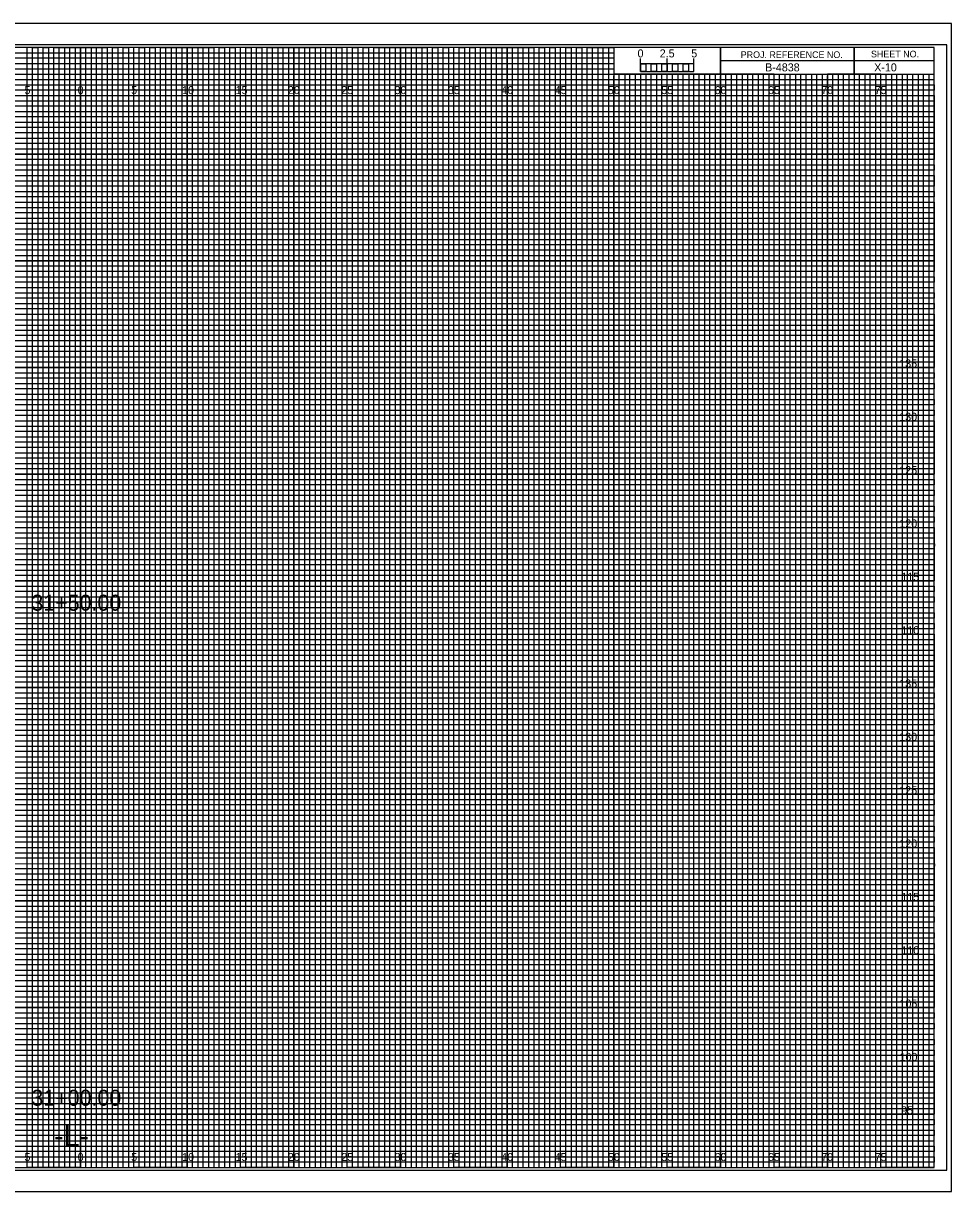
# Model space of a CAD drawing. Extents: x -7 to 182, y -2 to 1647.
# Drawn here: x 74.6 to 161.7, y 877.8 to 987.2 of the extents above; entities that cross this region are included whole.
import ezdxf

# ---------------------------------------------------------------- set-up
doc = ezdxf.new("R2010")
doc.units = 0
for name, color, linetype in [('Exist CMT Pavement', 7, 'Continuous'), ('Exist Cross Section Cell', 7, 'Continuous'), ('Exist XS Ground Line', 7, 'Continuous'), ('Prop CMT Pvmt Course 1', 7, 'Continuous'), ('Prop CMT Pvmt Course 2', 7, 'Continuous'), ('Prop CMT Pvmt Course 2 Wedge', 7, 'Continuous'), ('Prop CMT Pvmt Course 3', 7, 'Continuous'), ('Prop CMT Pvmt Surface', 7, 'Continuous'), ('Prop CMT Pvmt Surface Shoulder', 7, 'Continuous'), ('Prop CMT Pvmt Wedge Surface 1', 7, 'Continuous'), ('Prop CMT Pvmt Wedge Surface 2', 7, 'Continuous'), ('Prop CMT Pvmt Wedge Surface 3', 7, 'Continuous'), ('Prop CMT Shld Paved Course 1', 7, 'Continuous'), ('Prop CMT Shld Paved Course 2', 7, 'Continuous'), ('Prop CMT Shld Paved Course 3', 7, 'Continuous'), ('Prop CMT Slope Grass', 7, 'Continuous'), ('Prop CMT Subgrade Earthwork', 7, 'Continuous')]:
    doc.layers.add(name, color=color, linetype=linetype)

msp = doc.modelspace()

# ---------------------------------------------------------------- linework, layer by layer
at = {"layer": 'Exist XS Ground Line'}
for p, q in [((75, 985), (70, 985)), ((75, 880), (75, 985)), ((85, 985), (80, 985)), ((80, 985), (80, 880)), ((85, 880), (85, 985)), ((95, 985), (90, 985)), ((90, 985), (90, 880)), ((95, 880), (95, 985)), ((105, 985), (100, 985)), ((100, 985), (100, 880)), ((105, 880), (105, 985)), ((115, 985), (110, 985)), ((110, 985), (110, 880)), ((115, 880), (115, 985)), ((125, 985), (120, 985)), ((120, 985), (120, 880)), ((125, 880), (125, 985)), ((130, 985), (130, 880)), ((135, 880), (135, 982.5)), ((145, 982.5), (140, 982.5)), ((140, 982.5), (140, 880)), ((145, 880), (145, 982.5)), ((155, 982.5), (150, 982.5)), ((150, 982.5), (150, 880)), ((155, 880), (155, 982.5)), ((80, 880), (75, 880)), ((90, 880), (85, 880)), ((100, 880), (95, 880)), ((110, 880), (105, 880)), ((120, 880), (115, 880)), ((130, 880), (125, 880)), ((140, 880), (135, 880)), ((150, 880), (145, 880)), ((160, 880), (155, 880)), ((160, 880), (160, 880))]:
    msp.add_line(p, q, dxfattribs=at)
for points in [[(0, 980), (160, 980), (160, 975), (0, 975)], [(0, 970), (160, 970), (160, 965), (0, 965)], [(0, 960), (160, 960), (160, 955), (0, 955)], [(0, 950), (160, 950), (160, 945), (0, 945)], [(0, 940), (160, 940), (160, 935), (0, 935)], [(0, 930), (160, 930), (160, 925), (0, 925)], [(0, 920), (160, 920), (160, 915), (0, 915)], [(0, 910), (160, 910), (160, 905), (0, 905)], [(0, 900), (160, 900), (160, 895), (0, 895)], [(0, 890), (160, 890), (160, 885), (0, 885)]]:
    msp.add_lwpolyline(points, dxfattribs=at)
at = {"layer": 'Prop CMT Pvmt Course 2'}
for p, q in [((132.5, 982.75), (132.5, 983.95)), ((132.5, 983.45), (132.5, 983.95)), ((135, 982.75), (135, 983.95)), ((137.5, 982.75), (137.5, 983.95)), ((137.5, 983.45), (137.5, 983.95))]:
    msp.add_line(p, q, dxfattribs=at)
for points in [[(137.5, 983.45), (132.5, 983.45), (132.5, 982.75), (137.5, 982.75)], [(132.5, 983.45), (133, 983.45), (133, 982.75), (132.5, 982.75)], [(133.5, 983.45), (134, 983.45), (134, 982.75), (133.5, 982.75)], [(134.5, 983.45), (135, 983.45), (135, 982.75), (134.5, 982.75)], [(135.5, 983.45), (136, 983.45), (136, 982.75), (135.5, 982.75)], [(136.5, 983.45), (137, 983.45), (137, 982.75), (136.5, 982.75)]]:
    msp.add_lwpolyline(points, close=True, dxfattribs=at)
at = {"layer": 'Prop CMT Pvmt Course 3'}
msp.add_lwpolyline([(-6.7, 877.75), (161.65, 877.75), (161.65, 987.25), (-6.7, 987.25)], close=True, dxfattribs=at)
at = {"layer": 'Prop CMT Pvmt Wedge Surface 1'}
for p, q in [((0, 984.5), (130, 984.5)), ((130, 984.5), (130, 983.99)), ((130, 983.99), (0, 983.99)), ((0, 983.5), (130, 983.5)), ((130, 983.5), (130, 982.95)), ((130, 982.95), (0, 982.95)), ((0, 982), (160, 982))]:
    msp.add_line(p, q, dxfattribs=at)
for points in [[(0, 981.5), (135, 981.5), (160, 981.5), (160, 981), (0, 981)], [(0, 980.5), (160, 980.5), (160, 979.5), (0, 979.5)], [(0, 979), (160, 979), (160, 978.5), (0, 978.49)], [(0, 978), (160, 978), (160, 977), (0, 977)], [(0, 976.5), (160, 976.5), (160, 976), (0, 976)], [(0, 975.5), (160, 975.5), (160, 974.5), (0, 974.5)], [(0, 974), (160, 974), (160, 973.5), (0, 973.5)], [(0, 973), (160, 973), (160, 972), (0, 972)], [(0, 971.5), (160, 971.5), (160, 971), (0, 971)], [(0, 970.5), (160, 970.5), (160, 969.5), (0, 969.5)], [(0, 969), (160, 969), (160, 968.5), (0, 968.5)], [(0, 968), (160, 968), (160, 966.98), (160, 966.5), (160, 966), (0, 966)], [(0, 967), (160, 967), (160, 966.5), (0, 966.5)], [(0, 965.5), (160, 965.5), (160, 964.5), (0, 964.51)], [(0, 964.51), (160, 964.5), (160, 964), (0, 964)], [(0, 963.5), (160, 963.5), (160, 963), (0, 963)], [(0, 962), (160, 962), (160, 961.5), (0, 961.5)], [(0, 961), (160, 961), (160, 960.5), (0, 960.5)], [(-0.04, 959.45), (160, 959.45), (160, 958.94), (-0.04, 958.94)], [(0, 958.5), (160, 958.5), (160, 958), (0, 958)], [(0, 957), (160, 957), (160, 956.5), (0, 956.5)], [(0, 956), (160, 956), (160, 955.5), (0, 955.5)], [(0, 954.5), (160, 954.5), (160, 954), (0, 954)], [(0, 953.5), (160, 953.5), (160, 953), (0, 953)], [(0, 952), (160, 952), (160, 951.5), (0, 951.5)], [(0, 951), (160, 951), (160, 950.5), (0, 950.5)], [(0, 949.5), (160, 949.5), (160, 948.99), (0, 949)], [(0, 948.5), (160, 948.5), (160, 948), (0, 948)], [(0, 947), (160, 947), (160, 946.5), (0, 946.5)], [(0, 946), (160, 946), (160, 945.5), (0, 945.5)], [(0, 944.5), (160, 944.5), (160, 944), (0, 944)], [(0, 943.5), (160, 943.5), (160, 943), (0, 943)], [(0, 942), (160, 942), (160, 941.5), (0, 941.5)], [(0, 941), (160, 941), (160, 940.5), (0, 940.5)], [(0, 939.5), (160, 939.5), (160, 939), (0, 939)], [(0, 938.5), (160.03, 938.46), (160, 938), (0, 938)], [(0, 937), (160, 937), (160, 936.5), (0, 936.5)], [(0, 936), (160, 936), (160, 935.5), (0, 935.5)], [(0, 934.5), (160, 934.5), (160, 934), (0, 934)], [(0, 933.5), (160, 933.5), (160, 933), (0, 933)], [(0, 932), (160, 932), (160, 931.5), (0, 931.5)], [(0, 931), (160, 931), (160, 930.5), (0, 930.5)], [(0, 929.5), (160, 929.5), (160, 929), (0, 929)], [(0, 928.5), (160, 928.5), (160, 928), (0, 928)], [(0, 927), (160, 927), (160, 926.5), (0, 926.5)], [(0, 926), (160, 926), (160, 925.5), (0, 925.5)], [(0, 924.5), (160, 924.5), (160, 924), (0, 924)], [(0, 923.5), (160, 923.5), (160, 923), (0, 923)], [(0, 922), (160, 922), (160, 921.5), (0, 921.5)], [(0, 921), (160, 921), (160, 920.5), (0, 920.5)], [(0, 919.5), (160, 919.5), (160, 918.99), (0, 919)], [(0, 918.5), (160, 918.5), (160, 918), (0, 918)], [(0, 917), (160, 917), (160, 916.5), (0, 916.5)], [(0, 916), (160, 916), (160, 915.5), (0, 915.5)], [(0, 914.5), (160, 914.5), (160, 914), (0, 914)], [(0, 913.5), (160, 913.5), (160, 913), (0, 913)], [(0, 912), (160, 912), (160, 911.5), (0, 911.5)], [(0, 911), (160, 911), (160, 910.5), (0, 910.5)], [(0, 909.5), (160, 909.5), (160, 909), (0, 909)], [(0, 908.5), (160.03, 908.46), (160, 908), (0, 908)], [(0, 907), (160, 907), (160, 906.5), (0, 906.5)], [(0, 906), (160, 906), (160, 905.5), (0, 905.5)], [(0, 904.5), (160, 904.5), (160, 904), (0, 904)], [(0, 903.5), (160, 903.5), (160, 903), (0, 903)], [(0, 902), (160, 902), (160, 901.5), (0, 901.5)], [(0, 901), (160, 901), (160, 900.5), (0, 900.5)], [(0, 899.5), (160, 899.5), (160, 899), (0, 899)], [(0, 898.5), (160, 898.5), (160, 898), (0, 898)], [(0, 897), (160, 897), (160, 896.5), (0, 896.5)], [(0, 896), (160, 896), (160, 895.5), (0, 895.5)], [(0, 894.5), (160, 894.5), (160, 894), (0, 894)], [(0, 893.5), (160, 893.5), (160, 893), (0, 893)], [(0, 892), (160, 892), (160, 891.5), (0, 891.5)], [(0, 891), (160, 891), (160, 890.5), (0, 890.5)], [(0, 889.5), (160, 889.5), (160, 889), (0, 889)], [(0, 888.5), (160, 888.5), (160, 888), (0, 888)], [(0, 887), (160, 887), (160, 886.5), (0, 886.5)], [(0, 886), (160, 886), (160, 885.5), (0, 885.5)], [(0, 884.5), (160, 884.5), (160, 884), (0, 884)], [(0, 883.5), (160, 883.5), (160, 883), (0, 883)], [(0, 882), (160, 882), (160, 881.5), (0, 881.5)], [(0, 881), (160, 881), (160, 880.5), (0, 880.5)]]:
    msp.add_lwpolyline(points, dxfattribs=at)
at = {"layer": 'Prop CMT Pvmt Wedge Surface 2'}
for p, q in [((152.5, 985), (152.5, 982.5)), ((152.5, 982.5), (152.5, 985)), ((160, 983.75), (140, 983.75)), ((140, 983.75), (140, 982.5)), ((140, 982.5), (160, 982.5))]:
    msp.add_line(p, q, dxfattribs=at)
for points in [[(160, 985), (0, 985), (0, 880), (160, 880)], [(140, 985), (130, 985), (130, 982.51), (140, 982.51)], [(160, 985), (140, 985), (140, 982.5), (160, 982.5)]]:
    msp.add_lwpolyline(points, close=True, dxfattribs=at)
at = {"layer": 'Prop CMT Pvmt Wedge Surface 3'}
for p, q in [((133.5, 982.5), (133, 982.5)), ((133, 982.5), (133, 880)), ((133.5, 880), (133.5, 982.5)), ((134.5, 982.5), (134, 982.5)), ((134, 982.5), (134, 880)), ((134.5, 880), (134.5, 982.5)), ((133, 880), (132.5, 880)), ((134, 880), (133.5, 880))]:
    msp.add_line(p, q, dxfattribs=at)
for points in [[(75, 880), (75.5, 880), (75.5, 985), (76, 985), (76, 880)], [(76, 880), (76.5, 880), (76.5, 985), (77, 985), (77, 880)], [(77.5, 880), (78, 880), (78, 985), (78.5, 985), (78.5, 880)], [(78.5, 880), (79, 880), (79, 985), (79.5, 985), (79.5, 880)], [(80, 880), (80.5, 880), (80.5, 985), (81, 985), (81, 880)], [(81, 880), (81.5, 880), (81.5, 985), (82, 985), (82, 880)], [(82.5, 880), (83, 880), (83, 985), (83.5, 985), (83.5, 880)], [(83.5, 880), (84, 880), (84, 985), (84.5, 985), (84.5, 880)], [(85, 880), (85.5, 880), (85.5, 985), (86, 985), (86, 880)], [(86, 880), (86.5, 880), (86.5, 985), (87, 985), (87, 880)], [(87.5, 880), (88, 880), (88, 985), (88.5, 985), (88.5, 880)], [(88.5, 880), (89, 880), (89, 985), (89.5, 985), (89.5, 880)], [(90, 880), (90.5, 880), (90.5, 985), (91, 985), (91, 880)], [(91, 880), (91.5, 880), (91.5, 985), (92, 985), (92, 880)], [(92.5, 880), (93, 880), (93, 985), (93.5, 985), (93.5, 880)], [(93.5, 880), (94, 880), (94, 985), (94.5, 985), (94.5, 880)], [(95, 880), (95.5, 880), (95.5, 985), (96, 985), (96, 880)], [(96, 880), (96.5, 880), (96.5, 985), (97, 985), (97, 880)], [(97.5, 880), (98, 880), (98, 985), (98.5, 985), (98.5, 880)], [(98.5, 880), (99, 880), (99, 985), (99.5, 985), (99.5, 880)], [(100, 880), (100.5, 880), (100.5, 985), (101, 985), (101, 880)], [(101, 880), (101.5, 880), (101.5, 985), (102, 985), (102, 880)], [(102.5, 880), (103, 880), (103, 985), (103.5, 985), (103.5, 880)], [(103.5, 880), (104, 880), (104, 985), (104.5, 985), (104.5, 880)], [(105, 880), (105.5, 880), (105.5, 985), (106, 985), (106, 880)], [(106, 880), (106.5, 880), (106.5, 985), (107, 985), (107, 880)], [(107.5, 880), (108, 880), (108, 985), (108.5, 985), (108.5, 880)], [(108.5, 880), (109, 880), (109, 985), (109.5, 985), (109.5, 880)], [(110, 880), (110.5, 880), (110.5, 985), (111, 985), (111, 880)], [(111, 880), (111.5, 880), (111.5, 985), (112, 985), (112, 880)], [(112.5, 880), (113, 880), (113, 985), (113.5, 985), (113.5, 880)], [(113.5, 880), (114, 880), (114, 985), (114.5, 985), (114.5, 880)], [(115, 880), (115.5, 880), (115.5, 985), (116, 985), (116, 880)], [(116, 880), (116.5, 880), (116.5, 985), (117, 985), (117, 880)], [(117.5, 880), (118, 880), (118, 985), (118.5, 985), (118.5, 880)], [(118.5, 880), (119, 880), (119, 985), (119.5, 985), (119.5, 880)], [(120, 880), (120.5, 880), (120.5, 985), (121, 985), (121, 880)], [(121, 880), (121.5, 880), (121.5, 985), (122, 985), (122, 880)], [(122.5, 880), (123, 880), (123, 985), (123.5, 985), (123.5, 880)], [(123.5, 880), (124, 880), (124, 985), (124.5, 985), (124.5, 880)], [(125, 880), (125.5, 880), (125.5, 985), (126, 985), (126, 880)], [(126, 880), (126.5, 880), (126.5, 985), (127, 985), (127, 880)], [(127.5, 880), (128, 880), (128, 985), (128.5, 985), (128.5, 880)], [(128.5, 880), (129, 880), (129, 985), (129.5, 985), (129.5, 880)], [(130, 880), (130.5, 880), (130.5, 982.5), (131.01, 982.5), (131.01, 880)], [(131, 880), (131.5, 880), (131.5, 982.5), (132, 982.5), (132, 880)], [(135, 880), (135.49, 880), (135.49, 982.5), (136, 982.5), (136, 880)], [(136, 880), (136.5, 880), (136.5, 982.5), (137.03, 982.5), (137.03, 880)], [(137.5, 880), (138, 880), (138, 982.5), (138.5, 982.5), (138.5, 880)], [(138.5, 880), (139, 880), (139, 982.5), (139.5, 982.5), (139.5, 880)], [(140, 880), (140.5, 880), (140.5, 982.5), (141, 982.5), (141, 880)], [(141, 880), (141.5, 880), (141.5, 982.5), (142, 982.5), (142, 880)], [(142.5, 880), (143, 880), (143, 982.5), (143.5, 982.5), (143.5, 880)], [(143.5, 880), (144, 880), (144, 982.5), (144.5, 982.5), (144.5, 880)], [(145, 880), (145.5, 880), (145.5, 982.5), (146, 982.5), (146, 880)], [(146, 880), (146.5, 880), (146.5, 982.5), (147, 982.5), (147, 880)], [(147.5, 880), (148, 880), (148, 982.5), (148.5, 982.5), (148.5, 880)], [(148.5, 880), (149, 880), (149, 982.5), (149.5, 982.5), (149.5, 880)], [(150, 880), (150.5, 880), (150.5, 982.5), (151, 982.5), (151, 880)], [(151, 880), (151.5, 880), (151.5, 982.5), (152, 982.5), (152, 880)], [(152.5, 880), (153, 880), (153, 982.5), (153.5, 982.5), (153.5, 880)], [(153.5, 880), (154, 880), (154, 982.5), (154.5, 982.5), (154.5, 880)], [(155, 880), (155.5, 880), (155.5, 982.5), (156, 982.5), (156, 880)], [(156, 880), (156.5, 880), (156.5, 982.5), (157, 982.5), (157, 880)], [(157.5, 880), (158, 880), (158, 982.5), (158.5, 982.5), (158.5, 880)], [(158.5, 880), (159, 880), (159, 982.5), (159.5, 982.5), (159.5, 880)]]:
    msp.add_lwpolyline(points, dxfattribs=at)
at = {"layer": 'Prop CMT Shld Paved Course 1'}
for p, q in [((75, 880), (75, 985)), ((80, 880), (80, 985)), ((85, 880), (85, 985)), ((90, 880), (90, 985)), ((95, 880), (95, 985)), ((100, 880), (100, 985)), ((105, 880), (105, 985)), ((110, 880), (110, 985)), ((115, 880), (115, 985)), ((120, 880), (120, 985)), ((125, 880), (125, 985)), ((130, 880), (130, 982.34)), ((135, 880), (135, 982.34)), ((140, 880), (140, 982.34)), ((145, 880), (145, 982.34)), ((150, 880), (150, 982.34)), ((155, 880), (155, 982.34)), ((0, 980), (160, 980)), ((0, 975), (160, 975)), ((0, 970), (160, 970)), ((0, 965), (160, 965)), ((0, 960), (160, 960)), ((0, 955), (160, 955)), ((0, 950), (160, 950)), ((0, 945), (160, 945)), ((0, 940), (160, 940)), ((0, 935), (160, 935)), ((0, 930), (160, 930)), ((0, 925), (160, 925)), ((0, 920), (160, 920)), ((0, 915), (160, 915)), ((0, 910), (160, 910)), ((0, 905), (160, 905)), ((0, 900), (160, 900)), ((0, 895), (160, 895)), ((0, 890), (160, 890)), ((0, 885), (160, 885))]:
    msp.add_line(p, q, dxfattribs=at)
at = {"layer": 'Prop CMT Shld Paved Course 2'}
for p, q in [((161.65, 987.25), (-6.7, 987.25)), ((-6.7, 877.75), (161.65, 877.75))]:
    msp.add_line(p, q, dxfattribs=at)
at = {"layer": 'Prop CMT Slope Grass'}
msp.add_lwpolyline([(-5.4, 879.75), (161.2, 879.75), (161.2, 985.25), (-5.4, 985.25)], close=True, dxfattribs=at)
at = {"layer": 'Prop CMT Subgrade Earthwork'}
for points in [[(72.5, 880), (77.5, 880), (77.5, 985), (82.5, 985), (82.5, 880), (87.5, 880), (87.5, 985), (92.5, 985), (92.5, 880), (97.5, 880), (97.5, 985), (102.5, 985), (102.5, 880), (107.5, 880), (107.5, 985), (112.5, 985), (112.5, 880), (117.5, 880), (117.5, 985), (122.5, 985), (122.5, 880), (127.5, 880), (127.5, 985), (129.97, 985), (130, 985), (130, 982.5), (132.5, 982.5), (132.5, 880), (137.5, 880), (137.5, 982.5), (142.5, 982.5), (142.5, 880), (147.5, 880), (147.5, 982.5), (152.5, 982.5), (152.5, 880), (157.5, 880), (157.5, 982.5)], [(0, 982.5), (137.5, 982.5)], [(0, 972.5), (160, 972.5), (160, 977.5), (0, 977.5)], [(0, 962.5), (160, 962.5), (160, 967.5), (0, 967.5)], [(0, 952.5), (160, 952.5), (160, 957.5), (0, 957.5)], [(0, 942.5), (160, 942.5), (160, 947.5), (0, 947.5)], [(0, 932.5), (160, 932.5), (160, 937.5), (0, 937.5)], [(0, 922.5), (160, 922.5), (160, 927.5), (0, 927.5)], [(0, 912.5), (160, 912.5), (160, 917.5), (0, 917.5)], [(0, 902.5), (160, 902.5), (160, 907.5), (0, 907.5)], [(0, 892.5), (160, 892.5), (160, 897.5), (0, 897.5)], [(0, 882.5), (160, 882.5), (160, 887.5), (0, 887.5)]]:
    msp.add_lwpolyline(points, dxfattribs=at)

# ---------------------------------------------------------------- texts
at = {"layer": 'Exist CMT Pavement'}
for s, p in [('31+50.00', (75.39, 932.2)), ('31+00.00', (75.39, 885.8))]:
    msp.add_text(s, height=1.5, dxfattribs=at).set_placement(p)
at = {"layer": 'Exist Cross Section Cell'}
for s, p in [('5', (74.74, 980.62)), ('0', (79.73, 980.62)), ('0', (79.73, 980.62)), ('5', (84.74, 980.62)), ('10', (89.52, 980.62)), ('15', (94.53, 980.62)), ('20', (99.43, 980.62)), ('25', (104.44, 980.62)), ('30', (109.43, 980.62)), ('35', (114.44, 980.62)), ('40', (119.43, 980.62)), ('45', (124.44, 980.62)), ('50', (129.43, 980.62)), ('55', (134.44, 980.62)), ('60', (139.43, 980.62)), ('65', (144.44, 980.62)), ('70', (149.43, 980.62)), ('75', (154.44, 980.62)), ('5', (74.74, 880.62)), ('0', (79.73, 880.62)), ('0', (79.73, 880.62)), ('5', (84.74, 880.62)), ('10', (89.52, 880.62)), ('15', (94.53, 880.62)), ('20', (99.43, 880.62)), ('25', (104.44, 880.62)), ('30', (109.43, 880.62)), ('35', (114.44, 880.62)), ('40', (119.43, 880.62)), ('45', (124.44, 880.62)), ('50', (129.43, 880.62)), ('55', (134.44, 880.62)), ('60', (139.43, 880.62)), ('65', (144.44, 880.62)), ('70', (149.43, 880.62)), ('75', (154.44, 880.62))]:
    msp.add_text(s, height=0.75, dxfattribs=at).set_placement(p)
at = {"layer": 'Prop CMT Pvmt Course 1'}
msp.add_text('-L-', height=2, dxfattribs=at).set_placement((77.53, 882))
at = {"layer": 'Prop CMT Pvmt Course 2'}
msp.add_text('0', height=0.75, dxfattribs=at).set_placement((132.21, 984.06))
at = {"layer": 'Prop CMT Pvmt Course 2 Wedge'}
for s, p in [('2.5', (134.29, 984.06)), ('5', (137.24, 984.06))]:
    msp.add_text(s, height=0.75, dxfattribs=at).set_placement(p)
at = {"layer": 'Prop CMT Pvmt Surface'}
msp.add_text('X-10', height=0.75, dxfattribs=at).set_placement((154.39, 982.75))
at = {"layer": 'Prop CMT Pvmt Surface Shoulder'}
msp.add_text('B-4838', height=0.75, dxfattribs=at).set_placement((144.17, 982.75))
at = {"layer": 'Prop CMT Pvmt Wedge Surface 2'}
for s, p in [('PROJ. REFERENCE NO.', (141.88, 984)), ('SHEET NO.', (154.09, 984.06))]:
    msp.add_text(s, height=0.625, dxfattribs=at).set_placement(p)
at = {"layer": 'Prop CMT Shld Paved Course 3'}
for s, p in [('135', (156.74, 955)), ('130', (156.74, 950)), ('125', (156.74, 945)), ('120', (156.75, 940)), ('115', (156.93, 935)), ('110', (156.94, 930)), ('135', (156.74, 925)), ('130', (156.74, 920)), ('125', (156.74, 915)), ('120', (156.75, 910)), ('115', (156.93, 905)), ('110', (156.94, 900)), ('105', (156.76, 895)), ('100', (156.77, 890)), ('95', (156.92, 885))]:
    msp.add_text(s, height=0.75, dxfattribs=at).set_placement(p)

doc.saveas('drawing.dxf')
